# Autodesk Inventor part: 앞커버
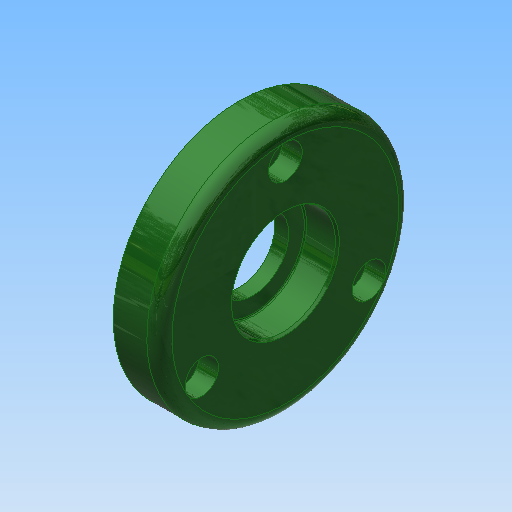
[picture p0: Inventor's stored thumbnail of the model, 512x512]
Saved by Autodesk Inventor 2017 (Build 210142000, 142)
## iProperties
Created: 2015-11
Part Number: 앞커버
Material: 알루미늄 6061
Document SubType Name: Modeling
Designer: mduedu
Density: 1 g/cm^3
Appearance: 매끄러움 - 짙은 산림 녹색
Author: mduedu
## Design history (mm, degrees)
sketch "스케치5"
  geometry: C1 r 30 at (0, 0); 2 further points
  constraints: 2 coincident, 1 centre point
  dimensions: "d66" = 60 diameter of C1
extrude "돌출2" new body sketch "스케치5" distance "d67" = 11; taper "d68" = 0 deg
sketch "스케치6"
  geometry: C1 r 16 at (0, 0); 1 further point
  constraints: 1 centre point, 1 coincident
  dimensions: "d69" = 32 diameter of C1
extrude "돌출3" join sketch "스케치6" distance "d70" = 3; taper "d71" = 0 deg
hole "구멍7" diameter "d98" = 27; stored, may be unused: countersink angle "d102" = 90 deg, drill point angle "d104" = 0 deg; dims "d99" = 6, "d100" = 4, "d101" = 2, "d103" = 3, "d143" = 10, "d144" = 10
hole "구멍8" diameter "d107" = 25; stored, may be unused: countersink angle "d111" = 90 deg, drill point angle "d113" = 0 deg; dims "d105" = 10, "d106" = 10, "d108" = 6, "d109" = 4, "d110" = 2, "d112" = 7.7
hole "구멍9" diameter "d116" = 17; stored, may be unused: countersink angle "d120" = 90 deg, drill point angle "d122" = 0 deg; dims "d114" = 10, "d115" = 10, "d117" = 6, "d118" = 4, "d119" = 2, "d121" = 7.7
chamfer "모따기2" distance "d123" = 0.6; stored, may be unused: second distance "d124" = 2, angle "d125" = 30 deg
fillet "모깎기11" dims "d126" = 0.3
fillet "모깎기13" dims "d128" = 3
fillet "모깎기14" dims "d129" = 3
fillet "모깎기15" dims "d130" = 0.3
sketch "스케치8" dims "d131" = 46
  geometry: 3 further points
  constraints: 2 vertical alignment, 1 coincident, 2 other
hole "구멍10" sketch "스케치8" at (0, 23) diameter "d132" = 4.5; stored, may be unused: countersink angle "d136" = 90 deg, drill point angle "d138" = 0 deg; dims "d133" = 6, "d134" = 8, "d135" = 4.6, "d137" = 7.7
node "솔리드2"
pattern_circular "원형 패턴4" dims angle "d140" = 360 deg
